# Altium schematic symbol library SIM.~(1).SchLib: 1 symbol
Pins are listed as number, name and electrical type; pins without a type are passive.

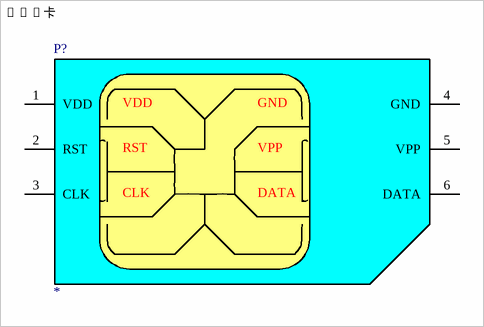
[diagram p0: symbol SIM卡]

## SIM卡
designator P?
footprint SIM卡 翻盖式
pins: 1 VDD, 2 RST, 3 CLK, 4 GND, 5 VPP, 6 DATA
2 alternate drawings of the same symbol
